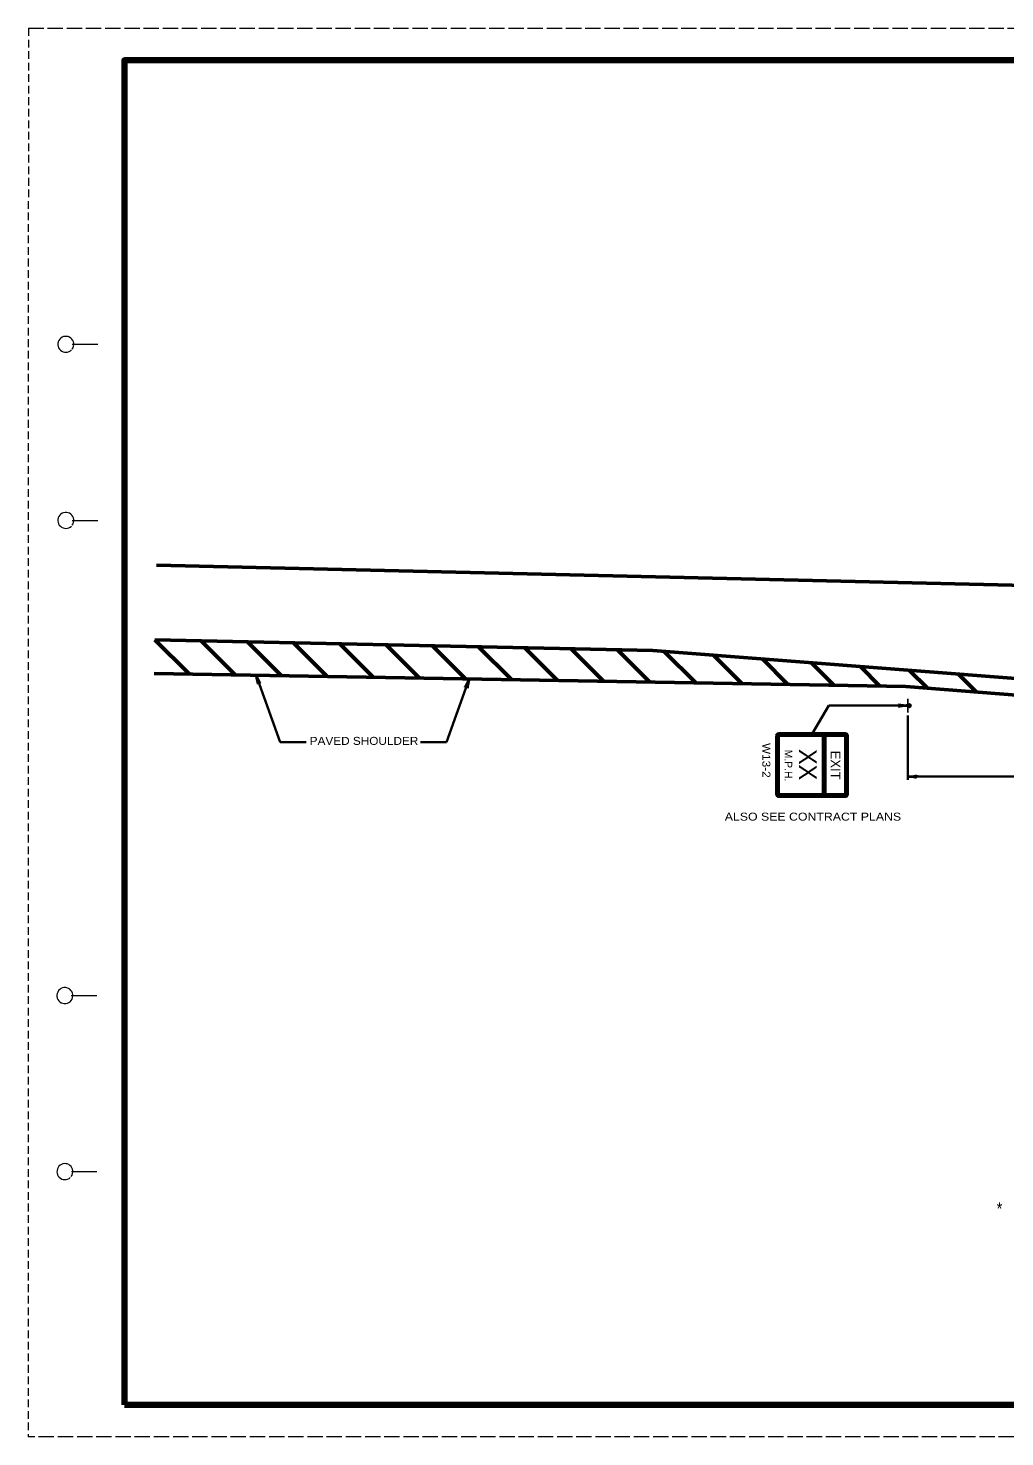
# Model space of a CAD drawing. Extents: x -281 to 399, y -258 to 182.
# Drawn here: x -280.7 to 24.5, y -258.5 to 181.6 of the extents above; entities that cross this region are included whole.
import ezdxf
from ezdxf.enums import TextEntityAlignment as Align

# ---------------------------------------------------------------- set-up
doc = ezdxf.new("R2010")
doc.units = 0
doc.header["$LTSCALE"] = 0.8
doc.linetypes.add('LONG_DASHED', pattern=[7.5, 6, -1.5])
doc.linetypes.add('MEDIUM_DASHED', pattern=[4.5, 3, -1.5])
for name, color, linetype, lineweight in [('1', 7, 'Continuous', 53), ('4', 7, 'Continuous', 25), ('61', 7, 'Continuous', 35)]:
    doc.layers.add(name, color=color, linetype=linetype, lineweight=lineweight)
doc.layers.add('2', color=7, linetype='Continuous')

msp = doc.modelspace()

# ---------------------------------------------------------------- hatches: boundary and pattern name
at = {"layer": '4'}
msp.add_hatch(color=256, dxfattribs=at).paths.add_polyline_path([(-5.3166, -30.6126, 1), (-5.3166, -29.5192, 1)])

# ---------------------------------------------------------------- linework, layer by layer
at = {"layer": '1', "linetype": 'MEDIUM_DASHED', "lineweight": 13}
msp.add_line((-280.6301, 181.553), (-280.6901, -258.487), dxfattribs=at)
at = {"layer": '1'}
for p, q in [((-240.6297, 13.7625), (36.2368, 7.2891)), ((-230.4283, -20.1821), (-241.1038, -9.5065)), ((-216.0338, -20.4344), (-226.6502, -9.818)), ((-201.6394, -20.6867), (-212.1967, -10.1294)), ((-187.245, -20.939), (-197.7431, -10.4409)), ((-172.8505, -21.1913), (-183.2895, -10.7523)), ((-158.4561, -21.4436), (-168.8359, -11.0638)), ((-144.0617, -21.6959), (-154.3823, -11.3752)), ((-129.6672, -21.9482), (-139.9287, -11.6867)), ((-115.2728, -22.2006), (-125.4751, -11.9982)), ((-100.8783, -22.4528), (-111.0215, -12.3097)), ((-86.4838, -22.7052), (-96.5679, -12.6211)), ((-72.0894, -22.9575), (-81.9092, -13.1377)), ((-57.695, -23.2097), (-66.584, -14.3208)), ((-43.3005, -23.4621), (-51.2588, -15.5038)), ((-28.9061, -23.7144), (-35.9337, -16.6867)), ((-14.5117, -23.9667), (-20.6086, -17.8697)), ((0.3011, -24.6373), (-5.2834, -19.0528)), ((15.6425, -25.8366), (10.0418, -20.2358))]:
    msp.add_line(p, q, dxfattribs=at)
at = {"layer": '1', "lineweight": 35}
for p, q in [((-142.8366, -21.7174), (-149.9741, -41.4371)), ((-35.7315, -38.8772), (-30.534, -30.0659)), ((-5.8499, -30.0659), (-30.534, -30.0659)), ((-5.8499, -33.1992), (-5.8499, -53.25)), ((-149.9741, -41.4371), (-158.088, -41.4371)), ((-5.8499, -52.25), (27.5809, -52.25))]:
    msp.add_line(p, q, dxfattribs=at)
at = {"layer": '1', "lineweight": 13}
for p, q in [((-46.6987, -57.8869), (-46.6987, -39.3647)), ((-46.2602, -38.8772), (-25.2028, -38.8772)), ((-24.7642, -39.3647), (-24.7642, -57.8869)), ((-25.2028, -58.3742), (-46.2602, -58.3742))]:
    msp.add_line(p, q, dxfattribs=at)
at = {"layer": '1', "lineweight": 70}
for p, q in [((-46.5338, -57.7447), (-46.5338, -39.5067)), ((-46.1319, -39.06), (-25.3308, -39.06)), ((-31.9575, -39.06), (-31.9575, -58.1916)), ((-24.9284, -39.5067), (-24.9284, -57.7447)), ((-25.3308, -58.1916), (-46.1319, -58.1916))]:
    msp.add_line(p, q, dxfattribs=at)
at = {"layer": '1'}
for points in [[(-241.1311, -9.5059), (-85.5166, -12.8592), (381.7234, -48.9276)], [(383.4217, -54.5876), (-6.4749, -24.1076), (-241.3148, -19.9913)]]:
    msp.add_lwpolyline(points, dxfattribs=at)
at = {"layer": '1', "lineweight": 35}
msp.add_lwpolyline([(-209.4632, -20.5496), (-201.9031, -41.4371), (-193.7892, -41.4371)], dxfattribs=at)
at = {"layer": '1', "lineweight": 40}
for centre, major_axis, ratio, start_param, end_param in [((-209.2809, -21.6752), (-0.4326, 1.7114), 0.07063, 3.14071475, 5.41810995), ((-209.2809, -21.6752), (-0.4326, 1.7114), 0.07063, 3.14071475, 5.41810995), ((-208.8321, -21.4816), (-0.7546, 1.626), 0.122415, 0.89635335, 3.14159265), ((-208.8321, -21.4816), (-0.7546, 1.626), 0.122415, 0.89635335, 3.14159265), ((-143.4169, -22.699), (0.763, 1.5918), 0.07063, 3.14071475, 5.41810995), ((-142.9482, -22.8375), (0.4609, 1.7322), 0.122415, 0.89635335, 3.14159265), ((-6.9411, -30.3422), (1.7857, 0.1562), 0.122415, 0.89635335, 3.14159265), ((-6.9704, -29.8543), (1.7565, -0.1757), 0.07063, 3.14071475, 5.41810995), ((-4.7294, -52.4616), (-1.7565, 0.1757), 0.07063, 3.14071475, 5.41810995), ((-4.7294, -52.4616), (-1.7565, 0.1757), 0.07063, 3.14071475, 5.41810995), ((-4.7587, -51.9737), (-1.7857, -0.1562), 0.122415, 0.89635335, 3.14159265), ((-4.7587, -51.9737), (-1.7857, -0.1562), 0.122415, 0.89635335, 3.14159265)]:
    msp.add_ellipse(centre, major_axis=major_axis, ratio=ratio, start_param=start_param, end_param=end_param, dxfattribs=at)
at = {"layer": '1', "lineweight": 13}
for centre, major_axis, start_param, end_param in [((-46.2598, -39.3646), (0, 0.4874), 6.28318531, 7.85398163), ((-25.2027, -39.3646), (0, 0.4874), 4.71238898, 6.28318531), ((-46.2598, -57.8869), (0, -0.4874), 4.71238898, 6.28318531), ((-25.2027, -57.8869), (0, 0.4874), 3.14159265, 4.71238898)]:
    msp.add_ellipse(centre, major_axis=major_axis, ratio=0.9, start_param=start_param, end_param=end_param, dxfattribs=at)
at = {"layer": '1', "lineweight": 70}
for centre, major_axis, start_param, end_param in [((-46.1318, -39.5067), (0, 0.4468), 6.28318531, 7.85398163), ((-25.3306, -39.5067), (0, 0.4468), 4.71238898, 6.28318531), ((-46.1318, -57.7447), (0, -0.4468), 4.71238898, 6.28318531), ((-25.3306, -57.7447), (0, 0.4468), 3.14159265, 4.71238898)]:
    msp.add_ellipse(centre, major_axis=major_axis, ratio=0.9, start_param=start_param, end_param=end_param, dxfattribs=at)
at = {"layer": '4'}
msp.add_line((-5.8499, -27.9326), (-5.8499, -32.1992), dxfattribs=at)
msp.add_circle((-5.3166, -30.0659), 0.5467, dxfattribs=at)
at = {"layer": '61', "linetype": 'LONG_DASHED', "lineweight": 13}
for p, q in [((-280.6301, 181.553), (399.3899, 181.553)), ((399.3699, -258.467), (-280.6901, -258.487))]:
    msp.add_line(p, q, dxfattribs=at)
at = {"layer": '61', "lineweight": 13}
for p, q in [((-266.9101, 82.793), (-258.9301, 82.813)), ((-266.9301, 27.793), (-258.9301, 27.793)), ((-267.2101, -120.627), (-259.2101, -120.627)), ((-267.1901, -175.647), (-259.2101, -175.647))]:
    msp.add_line(p, q, dxfattribs=at)
at = {"layer": '61', "lineweight": 158}
msp.add_line((388.4299, -248.487), (-250.6301, -248.467), dxfattribs=at)
msp.add_lwpolyline([(388.4099, 171.553), (-250.6301, 171.553), (-250.6301, -248.467)], dxfattribs=at)
at = {"layer": '61', "lineweight": 13}
for centre, start, end in [((-268.9323, 82.7943), 323.13009, 316.23216), ((-268.9323, 27.7943), 323.13009, 315.37577), ((-269.2123, -120.6457), 322.67175, 321.71615), ((-269.2123, -175.6457), 323.13009, 312.31439)]:
    msp.add_arc(centre, 2.5, start, end, dxfattribs=at)

# ---------------------------------------------------------------- texts
at = {"layer": '1', "width": 1.1}
msp.add_text('PAVED SHOULDER', height=2.5, dxfattribs=at).set_placement((-192.7072, -42.3389))
at = {"layer": '1'}
for s, height, p in [('XX', 5.445, (-39.7694, -48.4881)), ('M.P.H.', 2.42, (-44.3429, -48.785)), ('EXIT', 3.025, (-29.9042, -48.6632))]:
    msp.add_text(s, height=height, rotation=270, dxfattribs=at).set_placement(p, align=Align.CENTER)
msp.add_text('35', height=0.01522, rotation=269.642, dxfattribs=at).set_placement((-32.8815, -45.7832))
for s, height, width, p in [('ALSO SEE CONTRACT PLANS', 2.5, 1.15, (-35.4613, -66.0018)), ('*', 4, 0.85, (22.8154, -189.2223))]:
    msp.add_text(s, height=height, dxfattribs=dict(at, width=width)).set_placement(p, align=Align.CENTER)
at = {"layer": '2', "width": 1.1}
msp.add_text('W13-2', height=2.5, rotation=270, dxfattribs=at).set_placement((-51.2614, -47.1758), align=Align.CENTER)

doc.saveas('drawing.dxf')
